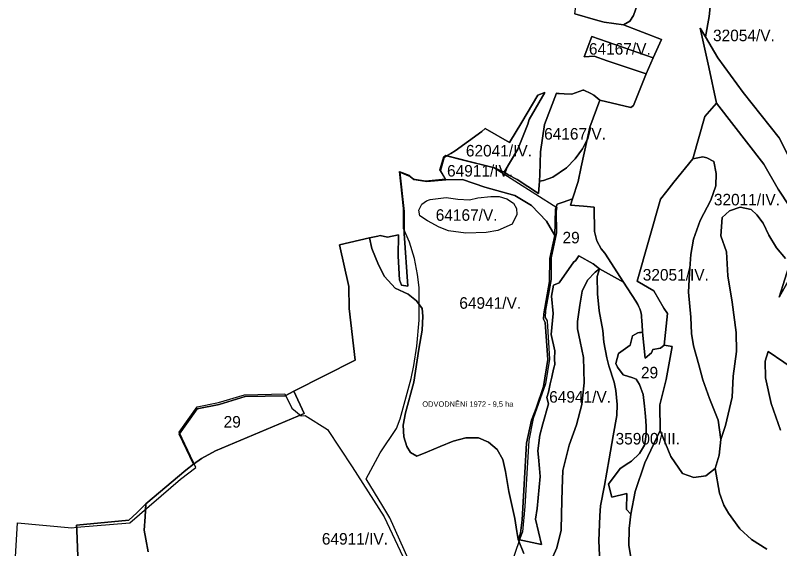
# Model space of a CAD drawing. Extents: x -521621 to -516761, y -1190184 to -1184927.
# Drawn here: x -519659 to -518666, y -1186696 to -1186003 of the extents above; entities that cross this region are included whole.
import ezdxf

# ---------------------------------------------------------------- set-up
doc = ezdxf.new("R2010")
doc.units = 0
doc.layers.add('BPEJ_s', color=7, linetype='Continuous')
doc.layers.add('odvodneni_s', color=7, linetype='Continuous')

msp = doc.modelspace()

# ---------------------------------------------------------------- linework, layer by layer
at = {"layer": 'BPEJ_s'}
for points in [[(-518927.24, -1185953.94), (-518919.2, -1185957.47), (-518903.58, -1185964.54), (-518887.75, -1185971.74), (-518858.33, -1185984.63), (-518853.23, -1185985.04), (-518849.62, -1185983.57), (-518850.9, -1185988.03), (-518856.42, -1186002.95), (-518861.03, -1186010.39), (-518869.09, -1186015.13), (-518894.47, -1186011.75), (-518902.58, -1186009.28), (-518932.52, -1186000.68), (-518929.68, -1185977.74), (-518926.98, -1185957.49)], [(-518839.76, -1186078.8), (-518890.62, -1186061.79), (-518907.36, -1186055.72), (-518920.21, -1186056.45), (-518910.27, -1186030.23), (-518830.77, -1186057.92)], [(-519099.23, -1186185.06), (-519093.67, -1186182.05), (-519087.79, -1186178.57), (-519053.23, -1186153.53), (-519049.1, -1186149.76), (-519017.53, -1186167.93), (-519001.26, -1186141.37), (-518980.5, -1186106.34), (-518971.45, -1186102.82), (-518991.71, -1186138.02), (-518993.72, -1186144.06), (-519006.47, -1186176.56), (-519024.12, -1186206.22), (-519036.73, -1186200.92), (-519078.87, -1186190.51)], [(-518978.56, -1186218.19), (-518977.87, -1186209.43), (-518977.14, -1186180.08), (-518971.74, -1186144.66), (-518956.26, -1186103.89), (-518954.89, -1186104.16), (-518952.82, -1186104.31), (-518946.24, -1186104.81), (-518936.52, -1186105.07), (-518922.31, -1186099.75), (-518920.92, -1186099.86), (-518911.74, -1186104.17), (-518907.96, -1186106.55), (-518900, -1186113.07), (-518913.14, -1186148.14), (-518916.35, -1186163.9), (-518922.7, -1186176.15), (-518932.15, -1186189.09), (-518943.34, -1186200.87), (-518960.9, -1186213.03), (-518973.06, -1186217.09)], [(-519100.11, -1186216.23), (-519106.93, -1186204.32), (-519102.12, -1186187.28), (-519099.23, -1186185.06), (-519078.87, -1186190.51), (-519036.73, -1186200.92), (-519024.12, -1186206.22), (-519018.33, -1186210.38), (-519007.58, -1186216.1), (-518979.81, -1186234.14), (-518978.56, -1186218.19), (-518973.06, -1186217.09), (-518960.9, -1186213.03), (-518943.34, -1186200.87), (-518932.15, -1186189.09), (-518922.7, -1186176.15), (-518916.35, -1186163.9), (-518924.26, -1186199.68), (-518928.29, -1186218.68), (-518935.71, -1186241.21), (-518947.84, -1186245.34), (-518955.44, -1186247.99), (-518957.48, -1186254.45), (-518958.55, -1186288.61), (-518969.39, -1186269.9), (-518988.69, -1186249.81), (-519010.3, -1186236.69), (-519049.28, -1186225.87), (-519078.61, -1186215.83)], [(-518821.82, -1186542.19), (-518822.21, -1186508.73), (-518813.91, -1186475.8), (-518805.93, -1186433.1), (-518816.66, -1186430.99), (-518812.11, -1186390.05), (-518816.88, -1186383.13), (-518829.78, -1186360.47), (-518851.51, -1186347.99), (-518821.34, -1186241.53), (-518813.03, -1186231.23), (-518803.71, -1186219.42), (-518779.14, -1186188.98), (-518766.43, -1186186.47), (-518760.84, -1186187.71), (-518752.15, -1186192.68), (-518748.95, -1186208.37), (-518749.28, -1186224.04), (-518755.95, -1186242.72), (-518769.61, -1186269.4), (-518778.28, -1186293.41), (-518781.94, -1186313.42), (-518783.61, -1186337.76), (-518784.94, -1186362.11), (-518781.61, -1186394.79), (-518780.94, -1186416.14), (-518778.28, -1186432.14), (-518771.61, -1186456.82), (-518766.28, -1186476.17), (-518757.6, -1186500.24), (-518746.34, -1186528.56), (-518742.69, -1186553.54), (-518745.12, -1186574.25), (-518749.99, -1186591.3), (-518762.47, -1186600.74), (-518778, -1186602.88), (-518792.61, -1186598), (-518807.83, -1186575.77)], [(-519199.32, -1186291.85), (-519188.43, -1186289.39), (-519185.21, -1186288.91), (-519175.79, -1186290.98), (-519161.77, -1186287.76), (-519162, -1186315.6), (-519160.16, -1186346.2), (-519157.86, -1186353.1), (-519149.59, -1186354.48), (-519154.05, -1186286.04), (-519154.05, -1186257.68), (-519159.74, -1186206.3), (-519146.35, -1186211.89), (-519141.76, -1186216.11), (-519124.9, -1186218.71), (-519100.11, -1186216.23), (-519078.61, -1186215.83), (-519049.28, -1186225.87), (-519010.3, -1186236.69), (-518988.69, -1186249.81), (-518969.39, -1186269.9), (-518958.55, -1186288.61), (-518964.97, -1186318.69), (-518965.37, -1186348.37), (-518972.98, -1186390.49), (-518973.26, -1186397.21), (-518970.84, -1186401.56), (-518967.71, -1186449.61), (-518973.02, -1186484.86), (-518982.62, -1186513.12), (-518988.81, -1186528.68), (-518995.15, -1186558.48), (-518997.41, -1186596.66), (-519000.81, -1186658.07), (-519003.05, -1186675.54), (-519006.29, -1186683.46), (-519007.95, -1186673.29), (-519010.28, -1186656.33), (-519018.25, -1186621.43), (-519022.57, -1186595.17), (-519026.22, -1186579.87), (-519033.2, -1186566.58), (-519044.83, -1186557.27), (-519057.45, -1186551.62), (-519074.06, -1186551.62), (-519090.34, -1186555.94), (-519107.62, -1186562.92), (-519123.9, -1186569.9), (-519137.85, -1186575.55), (-519145.83, -1186570.56), (-519150.81, -1186562.92), (-519154.8, -1186550.29), (-519155.46, -1186535), (-519152.47, -1186519.04), (-519141.84, -1186479.15), (-519135.19, -1186436.26), (-519130.72, -1186411.48), (-519130.11, -1186393.52), (-519131.03, -1186383.61), (-519138.15, -1186373.39), (-519148.98, -1186364.72), (-519166.01, -1186356.97), (-519179.62, -1186341.8), (-519187.67, -1186326.62), (-519196.03, -1186305.57)], [(-519030.98, -1186237.83), (-519020.92, -1186241.04), (-519012.32, -1186246.73), (-519008.38, -1186253.44), (-519007.66, -1186261.32), (-519013.93, -1186274.01), (-519032.59, -1186282.04), (-519047.75, -1186284.66), (-519074.14, -1186285.54), (-519096.6, -1186282.47), (-519108.56, -1186277.8), (-519123.72, -1186269.63), (-519133.78, -1186263.07), (-519135.24, -1186255.77), (-519131.45, -1186247.9), (-519125.32, -1186243.81), (-519120.3, -1186242.09), (-519099.84, -1186239.39), (-519084.4, -1186241.71), (-519069.35, -1186242.48), (-519058.55, -1186239.77), (-519041.56, -1186237.84)], [(-519030.98, -1186237.83), (-519020.92, -1186241.04), (-519012.32, -1186246.73), (-519008.38, -1186253.44), (-519007.66, -1186261.32), (-519013.93, -1186274.01), (-519032.59, -1186282.04), (-519047.75, -1186284.66), (-519074.14, -1186285.54), (-519096.6, -1186282.47), (-519108.56, -1186277.8), (-519123.72, -1186269.63), (-519133.78, -1186263.07), (-519135.24, -1186255.77), (-519131.45, -1186247.9), (-519125.32, -1186243.81), (-519120.3, -1186242.09), (-519099.84, -1186239.39), (-519084.4, -1186241.71), (-519069.35, -1186242.48), (-519058.55, -1186239.77), (-519041.56, -1186237.84)], [(-519006.29, -1186683.46), (-519003.05, -1186675.54), (-519000.81, -1186658.07), (-518997.41, -1186596.66), (-518995.15, -1186558.48), (-518988.81, -1186528.68), (-518982.62, -1186513.12), (-518973.02, -1186484.86), (-518967.71, -1186449.61), (-518970.84, -1186401.56), (-518973.26, -1186397.21), (-518972.98, -1186390.49), (-518965.37, -1186348.37), (-518964.97, -1186318.69), (-518958.55, -1186288.61), (-518957.48, -1186254.45), (-518955.44, -1186247.99), (-518947.84, -1186245.34), (-518935.71, -1186241.21), (-518938.33, -1186249.14), (-518921.14, -1186250.49), (-518907.24, -1186251.75), (-518906.8, -1186283.58), (-518903.75, -1186295.49), (-518898.38, -1186305.83), (-518893.45, -1186311.57), (-518869.16, -1186349.32), (-518900.51, -1186331.91), (-518908.64, -1186325.58), (-518927.41, -1186315.23), (-518931.81, -1186321.56), (-518933.69, -1186322.74), (-518953, -1186350.13), (-518960.15, -1186353.24), (-518962.63, -1186367.56), (-518960.61, -1186390.12), (-518963.46, -1186417.48), (-518958.46, -1186438.39), (-518958.72, -1186449.04), (-518958.59, -1186456.48), (-518959.62, -1186460.72), (-518961.41, -1186468.42), (-518962.57, -1186472.65), (-518964.36, -1186481.5), (-518966.76, -1186492.16), (-518968.74, -1186499.09), (-518966.56, -1186507.41), (-518974.08, -1186533.55), (-518977.84, -1186548.21), (-518980.41, -1186568.41), (-518979.62, -1186576.8), (-518978.46, -1186591.29), (-518977.49, -1186601.92), (-518981.55, -1186643.27), (-518983.43, -1186657.35), (-518975.63, -1186689.96)], [(-518859.55, -1186650.63), (-518865.37, -1186644.56), (-518864.88, -1186624.04), (-518884.37, -1186628.5), (-518888.84, -1186611.82), (-518873.77, -1186591.3), (-518862.41, -1186583.88), (-518858.99, -1186582.04), (-518848.36, -1186571.74), (-518842.15, -1186561.19), (-518840.85, -1186553.73), (-518840.02, -1186545.73), (-518839.63, -1186537.43), (-518840.09, -1186528.83), (-518840.93, -1186519.16), (-518842.07, -1186510.48), (-518843.67, -1186495.4), (-518848.46, -1186482.31), (-518852.84, -1186475.21), (-518857.37, -1186473.42), (-518869.66, -1186469.5), (-518877.07, -1186459.56), (-518879.12, -1186455.2), (-518875.79, -1186442.11), (-518860.41, -1186431.34), (-518857.75, -1186419.03), (-518850.72, -1186414.94), (-518848.43, -1186414.73), (-518846.9, -1186414.58), (-518844.45, -1186414.36), (-518841.34, -1186448.23), (-518832.8, -1186441.11), (-518831.24, -1186436.82), (-518821.02, -1186435.26), (-518816.66, -1186430.99), (-518805.93, -1186433.1), (-518813.91, -1186475.8), (-518822.21, -1186508.73), (-518821.82, -1186542.19), (-518841.54, -1186583.97), (-518854.04, -1186621.2)], [(-519428.09, -1186585.87), (-519446.7, -1186546.72), (-519423.19, -1186513.67), (-519394.66, -1186508.1), (-519360.57, -1186497.94), (-519308.81, -1186496.83), (-519297.4, -1186491.12), (-519284.1, -1186519.9), (-519399.26, -1186568.61), (-519417.63, -1186578.54)]]:
    msp.add_lwpolyline(points, close=True, dxfattribs=at)
for points in [[(-518755.34, -1185978.17), (-518758.01, -1186004.22), (-518762.89, -1186030.84), (-518769.77, -1186019.26), (-518758.59, -1186070.21), (-518748.37, -1186116.79), (-518763.55, -1186134.17), (-518779.14, -1186188.98), (-518803.71, -1186219.42), (-518813.03, -1186231.23), (-518821.34, -1186241.53), (-518851.51, -1186347.99), (-518829.78, -1186360.47), (-518816.88, -1186383.13), (-518812.11, -1186390.05), (-518816.66, -1186430.99), (-518821.02, -1186435.26), (-518831.24, -1186436.82), (-518832.8, -1186441.11), (-518841.34, -1186448.23), (-518844.45, -1186414.36), (-518844.61, -1186412.67), (-518845.46, -1186398.98), (-518845.71, -1186395), (-518845.93, -1186392.49), (-518846.44, -1186389.8), (-518847.28, -1186386.67), (-518848, -1186384.16), (-518849.29, -1186381.36), (-518850.52, -1186378.45), (-518851.91, -1186376.1), (-518853.37, -1186373.86), (-518869.16, -1186349.32), (-518893.45, -1186311.57), (-518898.38, -1186305.83), (-518903.75, -1186295.49), (-518906.8, -1186283.58), (-518907.24, -1186251.75), (-518921.14, -1186250.49), (-518938.33, -1186249.14), (-518935.71, -1186241.21), (-518928.29, -1186218.68), (-518924.26, -1186199.68), (-518916.35, -1186163.9), (-518913.14, -1186148.14), (-518900, -1186113.07), (-518876.03, -1186118.57), (-518859.72, -1186122.44), (-518856.24, -1186119.82), (-518839.76, -1186078.8), (-518830.77, -1186057.92), (-518819.98, -1186034.16), (-518869.09, -1186015.13), (-518861.03, -1186010.39), (-518856.42, -1186002.95), (-518850.9, -1185988.03)], [(-518632.34, -1186230.07), (-518666.87, -1186161.64), (-518713.8, -1186102.84), (-518746.89, -1186057.79), (-518762.89, -1186030.84), (-518758.01, -1186004.22), (-518755.34, -1185978.17)], [(-518932.52, -1186000.68), (-518902.58, -1186009.28), (-518894.47, -1186011.75), (-518869.09, -1186015.13), (-518819.98, -1186034.16), (-518830.77, -1186057.92), (-518910.27, -1186030.23), (-518920.21, -1186056.45), (-518907.36, -1186055.72), (-518890.62, -1186061.79), (-518839.76, -1186078.8), (-518856.24, -1186119.82), (-518859.72, -1186122.44), (-518876.03, -1186118.57), (-518900, -1186113.07), (-518907.96, -1186106.55), (-518911.74, -1186104.17), (-518920.92, -1186099.86), (-518922.31, -1186099.75), (-518936.52, -1186105.07), (-518946.24, -1186104.81), (-518952.82, -1186104.31), (-518954.89, -1186104.16), (-518956.26, -1186103.89), (-518971.74, -1186144.66), (-518977.14, -1186180.08), (-518977.87, -1186209.43), (-518978.56, -1186218.19), (-518979.81, -1186234.14), (-519007.58, -1186216.1), (-519018.33, -1186210.38), (-519024.12, -1186206.22), (-519006.47, -1186176.56), (-518993.72, -1186144.06), (-518991.71, -1186138.02), (-518971.45, -1186102.82), (-518980.5, -1186106.34), (-519001.26, -1186141.37), (-519017.53, -1186167.93), (-519049.1, -1186149.76), (-519053.23, -1186153.53), (-519087.79, -1186178.57), (-519093.67, -1186182.05), (-519099.23, -1186185.06), (-519102.12, -1186187.28), (-519106.93, -1186204.32), (-519100.11, -1186216.23), (-519124.9, -1186218.71), (-519141.76, -1186216.11), (-519146.35, -1186211.89), (-519159.74, -1186206.3), (-519154.05, -1186257.68), (-519154.05, -1186286.04), (-519149.59, -1186354.48), (-519157.86, -1186353.1), (-519160.16, -1186346.2), (-519162, -1186315.6), (-519161.77, -1186287.76), (-519175.79, -1186290.98), (-519185.21, -1186288.91), (-519188.43, -1186289.39), (-519199.32, -1186291.85), (-519238.33, -1186300.66), (-519226.01, -1186354.88), (-519225.76, -1186383.49), (-519218.04, -1186450.6), (-519297.4, -1186491.12), (-519308.81, -1186496.83), (-519360.57, -1186497.94), (-519394.66, -1186508.1), (-519423.19, -1186513.67), (-519446.7, -1186546.72), (-519428.09, -1186585.87), (-519437.8, -1186593.43), (-519489.59, -1186637.44), (-519496.75, -1186644.17), (-519501.39, -1186648.96), (-519511.68, -1186658.53), (-519579.94, -1186664.8), (-519579.64, -1186671.38), (-519573.71, -1186819.93)], [(-518653.25, -1186251.43), (-518668.53, -1186228.68), (-518686.91, -1186196.11), (-518748.37, -1186116.79), (-518758.59, -1186070.21), (-518769.77, -1186019.26), (-518762.89, -1186030.84), (-518746.89, -1186057.79), (-518713.8, -1186102.84), (-518666.87, -1186161.64), (-518632.34, -1186230.07)], [(-518658.79, -1186318.79), (-518670.73, -1186304.88), (-518680.29, -1186288.27), (-518687.96, -1186272.73), (-518695.95, -1186262.06), (-518703.29, -1186255.06), (-518717.62, -1186252.06), (-518731.62, -1186256.73), (-518740.95, -1186265.4), (-518742.95, -1186289.07), (-518735.62, -1186310.08), (-518733.62, -1186341.1), (-518728.28, -1186375.45), (-518722.95, -1186414.8), (-518722.28, -1186439.48), (-518726.95, -1186471.5), (-518728.28, -1186498.84), (-518736.95, -1186535.53), (-518742.69, -1186553.54), (-518746.34, -1186528.56), (-518757.6, -1186500.24), (-518766.28, -1186476.17), (-518771.61, -1186456.82), (-518778.28, -1186432.14), (-518780.94, -1186416.14), (-518781.61, -1186394.79), (-518784.94, -1186362.11), (-518783.61, -1186337.76), (-518781.94, -1186313.42), (-518778.28, -1186293.41), (-518769.61, -1186269.4), (-518755.95, -1186242.72), (-518749.28, -1186224.04), (-518748.95, -1186208.37), (-518752.15, -1186192.68), (-518760.84, -1186187.71), (-518766.43, -1186186.47), (-518779.14, -1186188.98), (-518763.55, -1186134.17), (-518748.37, -1186116.79), (-518686.91, -1186196.11), (-518668.53, -1186228.68), (-518653.25, -1186251.43)], [(-518682.95, -1186696.15), (-518702.98, -1186683.73), (-518718.22, -1186669.9), (-518732.89, -1186649.57), (-518738.73, -1186638.81), (-518744.51, -1186623.59), (-518749.99, -1186591.3), (-518745.12, -1186574.25), (-518742.69, -1186553.54), (-518736.95, -1186535.53), (-518728.28, -1186498.84), (-518726.95, -1186471.5), (-518722.28, -1186439.48), (-518722.95, -1186414.8), (-518728.28, -1186375.45), (-518733.62, -1186341.1), (-518735.62, -1186310.08), (-518742.95, -1186289.07), (-518740.95, -1186265.4), (-518731.62, -1186256.73), (-518717.62, -1186252.06), (-518703.29, -1186255.06), (-518695.95, -1186262.06), (-518687.96, -1186272.73), (-518680.29, -1186288.27), (-518670.73, -1186304.88), (-518658.79, -1186318.79)], [(-519486.64, -1186699.48), (-519489.73, -1186683.38), (-519491.9, -1186671.61), (-519490.66, -1186654.27), (-519489.59, -1186637.44), (-519437.8, -1186593.43), (-519428.09, -1186585.87), (-519417.63, -1186578.54), (-519399.26, -1186568.61), (-519284.1, -1186519.9), (-519297.4, -1186491.12), (-519218.04, -1186450.6), (-519225.76, -1186383.49), (-519226.01, -1186354.88), (-519238.33, -1186300.66), (-519199.32, -1186291.85), (-519196.03, -1186305.57), (-519187.67, -1186326.62), (-519179.62, -1186341.8), (-519166.01, -1186356.97), (-519148.98, -1186364.72), (-519138.15, -1186373.39), (-519131.03, -1186383.61), (-519130.11, -1186393.52), (-519130.72, -1186411.48), (-519135.19, -1186436.26), (-519141.84, -1186479.15), (-519152.47, -1186519.04), (-519155.46, -1186535), (-519154.8, -1186550.29), (-519150.81, -1186562.92), (-519145.83, -1186570.56), (-519137.85, -1186575.55), (-519123.9, -1186569.9), (-519107.62, -1186562.92), (-519090.34, -1186555.94), (-519074.06, -1186551.62), (-519057.45, -1186551.62), (-519044.83, -1186557.27), (-519033.2, -1186566.58), (-519026.22, -1186579.87), (-519022.57, -1186595.17), (-519018.25, -1186621.43), (-519010.28, -1186656.33), (-519007.95, -1186673.29), (-519006.29, -1186683.46), (-518998.65, -1186701.88)], [(-518998.65, -1186701.88), (-519006.29, -1186683.46), (-518975.63, -1186689.96), (-518983.43, -1186657.35), (-518981.55, -1186643.27), (-518977.49, -1186601.92), (-518978.46, -1186591.29), (-518979.62, -1186576.8), (-518980.41, -1186568.41), (-518977.84, -1186548.21), (-518974.08, -1186533.55), (-518966.56, -1186507.41), (-518968.74, -1186499.09), (-518966.76, -1186492.16), (-518964.36, -1186481.5), (-518962.57, -1186472.65), (-518961.41, -1186468.42), (-518959.62, -1186460.72), (-518958.59, -1186456.48), (-518958.72, -1186449.04), (-518958.46, -1186438.39), (-518963.46, -1186417.48), (-518960.61, -1186390.12), (-518962.63, -1186367.56), (-518960.15, -1186353.24), (-518953, -1186350.13), (-518933.69, -1186322.74), (-518931.81, -1186321.56), (-518927.41, -1186315.23), (-518908.64, -1186325.58), (-518900.51, -1186331.91), (-518906.18, -1186336.23), (-518916.25, -1186346.52), (-518922.89, -1186361.09), (-518926.1, -1186379.31), (-518929.1, -1186400.52), (-518928.86, -1186409.78), (-518925.56, -1186426.62), (-518921.24, -1186447.24), (-518920.24, -1186480.15), (-518923.56, -1186508.4), (-518930.21, -1186534.67), (-518939.84, -1186561.26), (-518948.15, -1186593.84), (-518949.15, -1186617.77), (-518949.81, -1186650.35), (-518950.14, -1186671.62), (-518955.79, -1186694.23), (-518963.1, -1186710.85)], [(-518649.43, -1186337.23), (-518667.13, -1186369), (-518652.28, -1186322.17)], [(-518652.28, -1186322.17), (-518667.13, -1186369), (-518649.43, -1186337.23)], [(-518963.1, -1186710.85), (-518955.79, -1186694.23), (-518950.14, -1186671.62), (-518949.81, -1186650.35), (-518949.15, -1186617.77), (-518948.15, -1186593.84), (-518939.84, -1186561.26), (-518930.21, -1186534.67), (-518923.56, -1186508.4), (-518920.24, -1186480.15), (-518921.24, -1186447.24), (-518925.56, -1186426.62), (-518928.86, -1186409.78), (-518929.1, -1186400.52), (-518926.1, -1186379.31), (-518922.89, -1186361.09), (-518916.25, -1186346.52), (-518906.18, -1186336.23), (-518900.51, -1186331.91), (-518903.4, -1186342.02), (-518903.19, -1186364.52), (-518900.83, -1186386.38), (-518896.11, -1186412.13), (-518894.69, -1186427.31), (-518890.85, -1186447.75), (-518888.22, -1186458.07), (-518881.34, -1186479.33), (-518879.32, -1186490.26), (-518877.5, -1186508.27), (-518878.11, -1186522.44), (-518882.66, -1186548.86), (-518887.92, -1186578.81), (-518893.97, -1186613.54), (-518899.14, -1186640.03), (-518899.89, -1186653.03), (-518901.18, -1186685.21), (-518899.4, -1186722.39)], [(-518899.4, -1186722.39), (-518901.18, -1186685.21), (-518899.89, -1186653.03), (-518899.14, -1186640.03), (-518893.97, -1186613.54), (-518887.92, -1186578.81), (-518882.66, -1186548.86), (-518878.11, -1186522.44), (-518877.5, -1186508.27), (-518879.32, -1186490.26), (-518881.34, -1186479.33), (-518888.22, -1186458.07), (-518890.85, -1186447.75), (-518894.69, -1186427.31), (-518896.11, -1186412.13), (-518900.83, -1186386.38), (-518903.19, -1186364.52), (-518903.4, -1186342.02), (-518900.51, -1186331.91), (-518869.16, -1186349.32), (-518853.37, -1186373.86), (-518851.91, -1186376.1), (-518850.52, -1186378.45), (-518849.29, -1186381.36), (-518848, -1186384.16), (-518847.28, -1186386.67), (-518846.44, -1186389.8), (-518845.93, -1186392.49), (-518845.71, -1186395), (-518845.46, -1186398.98), (-518844.61, -1186412.67), (-518844.45, -1186414.36), (-518846.9, -1186414.58), (-518848.43, -1186414.73), (-518850.72, -1186414.94), (-518857.75, -1186419.03), (-518860.41, -1186431.34), (-518875.79, -1186442.11), (-518879.12, -1186455.2), (-518877.07, -1186459.56), (-518869.66, -1186469.5), (-518857.37, -1186473.42), (-518852.84, -1186475.21), (-518848.46, -1186482.31), (-518843.67, -1186495.4), (-518842.07, -1186510.48), (-518840.93, -1186519.16), (-518840.09, -1186528.83), (-518839.63, -1186537.43), (-518840.02, -1186545.73), (-518840.85, -1186553.73), (-518842.15, -1186561.19), (-518848.36, -1186571.74), (-518858.99, -1186582.04), (-518862.41, -1186583.88), (-518873.77, -1186591.3), (-518888.84, -1186611.82), (-518884.37, -1186628.5), (-518864.88, -1186624.04), (-518865.37, -1186644.56), (-518859.55, -1186650.63), (-518861.94, -1186669.42), (-518862.19, -1186691.23), (-518857.93, -1186716.79)], [(-518665.44, -1186541.44), (-518677.5, -1186506.82), (-518684.8, -1186473.48), (-518685.12, -1186451.89), (-518681.31, -1186439.5), (-518640.68, -1186467.13)], [(-518640.68, -1186467.13), (-518681.31, -1186439.5), (-518685.12, -1186451.89), (-518684.8, -1186473.48), (-518677.5, -1186506.82), (-518665.44, -1186541.44)], [(-518857.93, -1186716.79), (-518862.19, -1186691.23), (-518861.94, -1186669.42), (-518859.55, -1186650.63), (-518854.04, -1186621.2), (-518841.54, -1186583.97), (-518821.82, -1186542.19), (-518807.83, -1186575.77), (-518792.61, -1186598), (-518778, -1186602.88), (-518762.47, -1186600.74), (-518749.99, -1186591.3), (-518744.51, -1186623.59), (-518738.73, -1186638.81), (-518732.89, -1186649.57), (-518718.22, -1186669.9), (-518702.98, -1186683.73), (-518682.95, -1186696.15)], [(-519573.71, -1186819.93), (-519579.64, -1186671.38), (-519579.94, -1186664.8), (-519511.68, -1186658.53), (-519501.39, -1186648.96), (-519496.75, -1186644.17), (-519489.59, -1186637.44), (-519490.66, -1186654.27), (-519491.9, -1186671.61), (-519489.73, -1186683.38), (-519486.64, -1186699.48)]]:
    msp.add_lwpolyline(points, dxfattribs=at)
at = {"layer": 'odvodneni_s'}
for points in [[(-519146.97, -1186713.39), (-519172.87, -1186655.43), (-519181.8, -1186640.27), (-519203.78, -1186604.96), (-519185.38, -1186571.06), (-519164.11, -1186539.61), (-519159.22, -1186526.76), (-519145.26, -1186474.27), (-519141.63, -1186457.51), (-519137.72, -1186432.38), (-519134.65, -1186398.87), (-519134.79, -1186356.15), (-519136.74, -1186339.39), (-519140.65, -1186318.45), (-519147.35, -1186297.51), (-519155.12, -1186279.58), (-519155.23, -1186253.66), (-519160.22, -1186205.67), (-519147.55, -1186210.53), (-519142.68, -1186215.27), (-519126.43, -1186217.83), (-519100.71, -1186215.27), (-519107.75, -1186203.36), (-519102.88, -1186185.96), (-519099.94, -1186184.55), (-519037.61, -1186200.42), (-518955.84, -1186252.51), (-518956.7, -1186257.06), (-518956.16, -1186285.13), (-518963.41, -1186317.85), (-518963.14, -1186345.78), (-518970.67, -1186386.18), (-518971.22, -1186395.35), (-518968.48, -1186399.46), (-518965.6, -1186449.57), (-518970.4, -1186481.48), (-518986.42, -1186526.39), (-518992.3, -1186555.14), (-518997.37, -1186640.58), (-519000.38, -1186673.45), (-519003.53, -1186681.39), (-519051.29, -1186821.65)], [(-519659.38, -1186713.47), (-519656.68, -1186661.93), (-519585.89, -1186668.25), (-519579.3, -1186667.47), (-519510.6, -1186661.84), (-519444.92, -1186605.18), (-519424.94, -1186590.05), (-519427.77, -1186583.63), (-519446.56, -1186544.32), (-519422.97, -1186511.24), (-519395.3, -1186505.72), (-519361.81, -1186495.82), (-519309.12, -1186494.49), (-519300.33, -1186512.97), (-519288.1, -1186523.04), (-519282.73, -1186522.69), (-519253.62, -1186540.63), (-519221.82, -1186589.06), (-519180.32, -1186653.96), (-519107.8, -1186808)]]:
    msp.add_lwpolyline(points, dxfattribs=at)

# ---------------------------------------------------------------- texts
at = {"layer": 'BPEJ_s'}
for s, p in [('32054/V.', (-518752.99, -1186036.32)), ('64167/V.', (-518914.2, -1186053.77)), ('64167/V.', (-518972.38, -1186164.12)), ('62041/IV.', (-519074.03, -1186186.05)), ('64911/IV.', (-519098.53, -1186212.13)), ('32011/IV.', (-518751.86, -1186249.58)), ('64167/V.', (-519113.21, -1186269.63)), ('29', (-518948.52, -1186298.94)), ('32051/IV.', (-518844.28, -1186347.27)), ('64941/V.', (-519082.55, -1186383.89)), ('29', (-518846.61, -1186474.31)), ('64941/V.', (-518965.81, -1186505.87)), ('29', (-519388.73, -1186538.25)), ('35900/III.', (-518879.57, -1186560.18)), ('64911/IV.', (-519261.12, -1186690.26))]:
    msp.add_text(s, height=15, dxfattribs=at).set_placement(p)
at = {"layer": 'odvodneni_s'}
msp.add_text('ODVODNĚNí 1972 - 9,5 ha', height=7, dxfattribs=at).set_placement((-519130.6, -1186511.21))

doc.saveas('drawing.dxf')
